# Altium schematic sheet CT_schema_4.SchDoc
size 312 x 238 mm
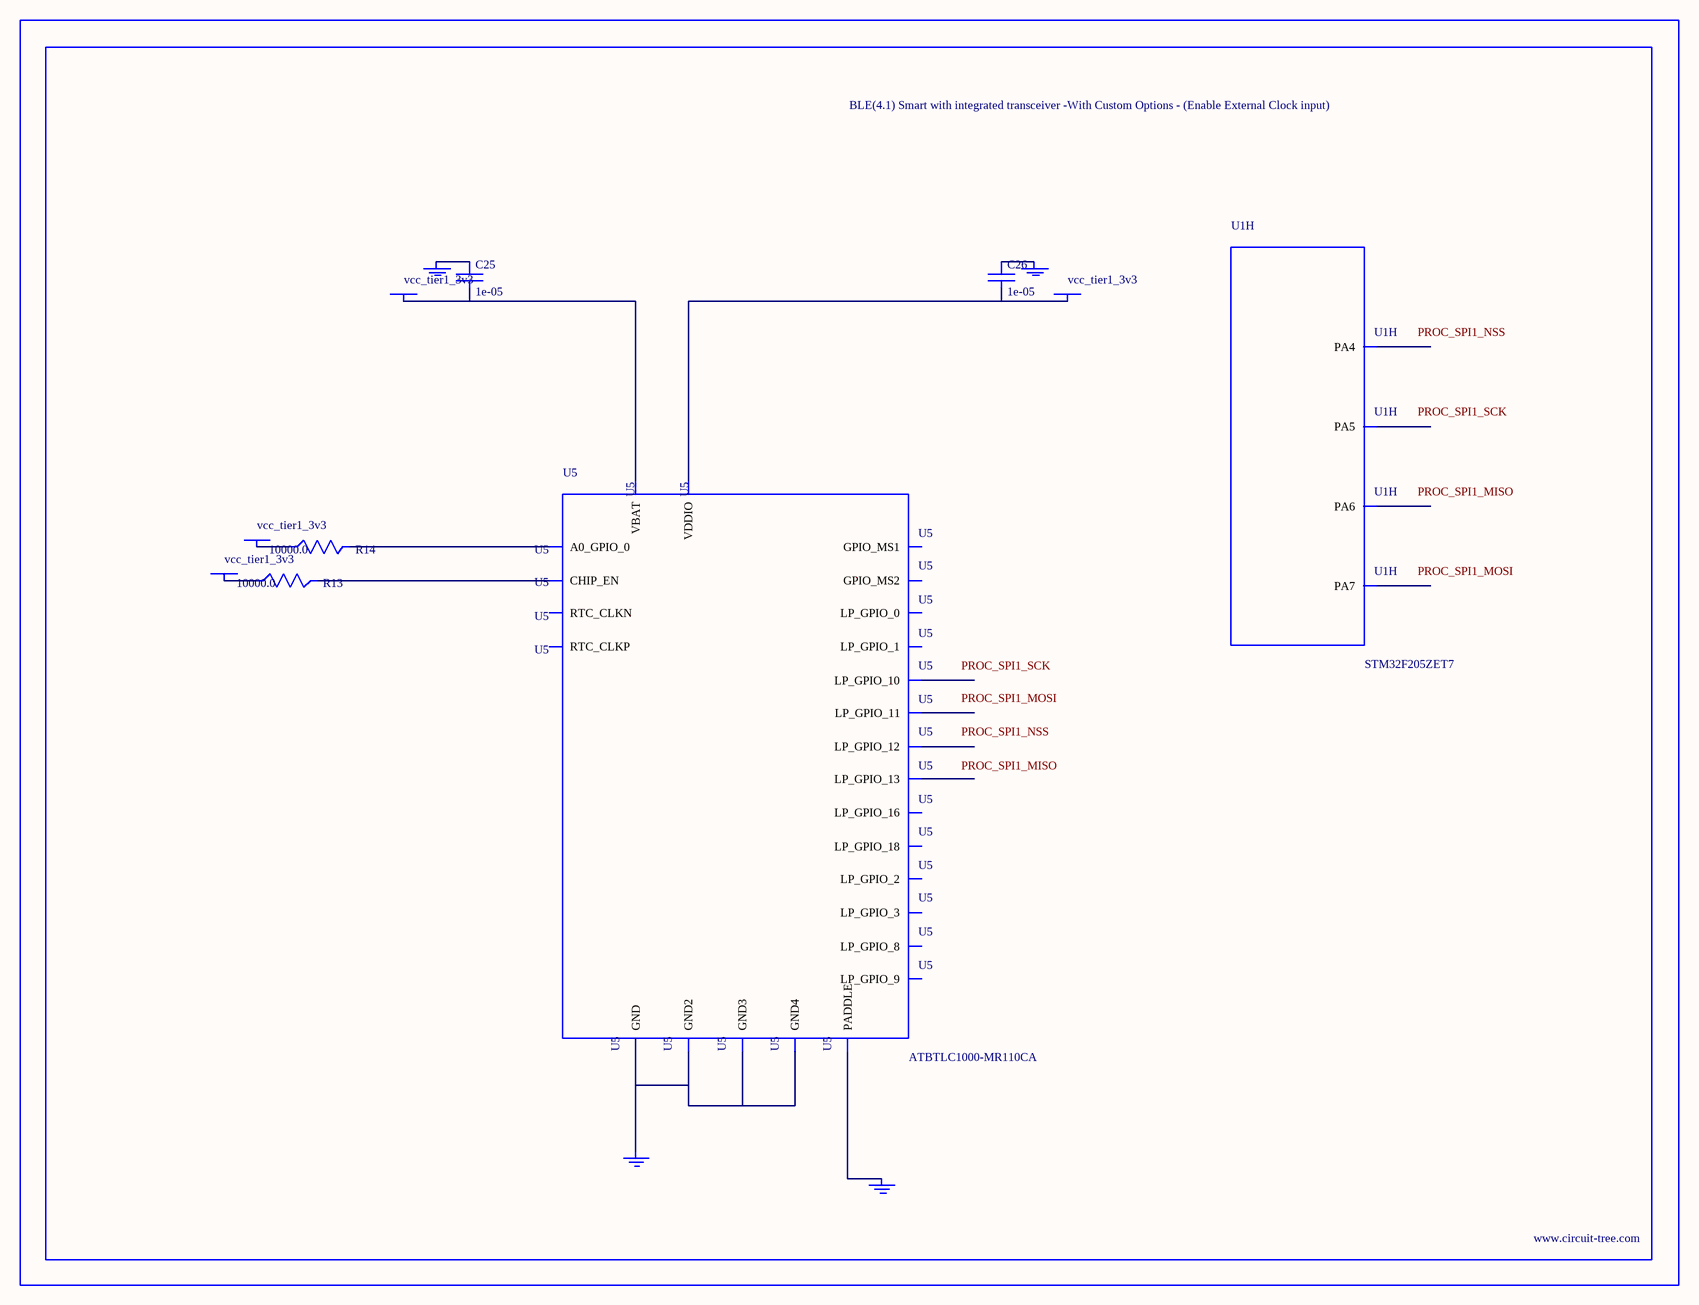
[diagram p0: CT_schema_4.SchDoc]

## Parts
BORDER3  (no value)
C25  1e-05  [C0805]
C26  1e-05  [C0805]
GND_INSTANCE_3_0  (no value)
GND_INSTANCE_3_1  (no value)
GND_INSTANCE_3_2  (no value)
GND_INSTANCE_3_3  (no value)
POWER_INSTANCE_3_0  vcc_tier1_3v3
POWER_INSTANCE_3_1  vcc_tier1_3v3
POWER_INSTANCE_3_2  vcc_tier1_3v3
POWER_INSTANCE_3_3  vcc_tier1_3v3
R13  10000.0  [R0603]
R14  10000.0  [R0603]
U1  STM32F205ZET7  [LQFP144]  (part H of 13)
U5  ATBTLC1000-MR110CA  [ATBTLC1000-MR110CA]

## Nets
NetC25_1: C25.1 GND_INSTANCE_3_0.0(GND)
NetC25_2: C25.2 POWER_INSTANCE_3_0.0(PWR) U5.6(VBAT)
NetC26_1: C26.1 GND_INSTANCE_3_1.0(GND)
NetC26_2: C26.2 POWER_INSTANCE_3_3.0(PWR) U5.22(VDDIO)
NetGND_INSTANCE_3_2_0: GND_INSTANCE_3_2.0(GND) U5.25(PADDLE)
NetGND_INSTANCE_3_3_0: GND_INSTANCE_3_3.0(GND) U5.1(GND) U5.9(GND2) U5.13(GND3) U5.24(GND4)
NetPOWER_INSTANCE_3_1_0: POWER_INSTANCE_3_1.0(PWR) R13.1
NetPOWER_INSTANCE_3_2_0: POWER_INSTANCE_3_2.0(PWR) R14.1
NetR13_2: R13.2 U5.17(CHIP_EN)
NetR14_2: R14.2 U5.20(A0_GPIO_0)

Not connected (* = marked no-connect by the designer): U1 40(PA4) 41(PA5) 42(PA6) 43(PA7); U5 2(LP_GPIO_0) 3(LP_GPIO_1) 4(LP_GPIO_2) 5(LP_GPIO_3) 7(LP_GPIO_8) 8(LP_GPIO_9) 10(LP_GPIO_10) 11(LP_GPIO_11) 12(LP_GPIO_12) 14(LP_GPIO_13) 15(GPIO_MS1) 16(GPIO_MS2) 18(RTC_CLKP) 19(RTC_CLKN) 21(LP_GPIO_16) 23(LP_GPIO_18)

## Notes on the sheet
- Labels drawn without touching a wire or pin: PROC_SPI1_MISO, PROC_SPI1_MOSI, PROC_SPI1_NSS, PROC_SPI1_SCK

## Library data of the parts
BORDER3 = BORDER_PAGE3
C25 C26 = C0805C106K8RACTU
GND_INSTANCE_3_0-GND_INSTANCE_3_3 = GND
POWER_INSTANCE_3_0-POWER_INSTANCE_3_3 = PWR
R13 R14 = RC0603JR-0710KL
